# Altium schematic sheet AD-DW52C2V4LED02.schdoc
size 127 x 101 mm
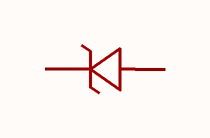
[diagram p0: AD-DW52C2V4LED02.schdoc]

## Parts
D?  ad-dw52c2v4led02  [WBFBP-02C_L1.0-W0.6-RD]  (value not drawn)

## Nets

Not connected (* = marked no-connect by the designer): D? 1(A) 2(C)

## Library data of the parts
D? = ad-dw52c2v4led02: 二极管配置:1个独立式;稳压值(标称值):2.4V;稳压值(范围值):2.2V~2.6V;耗散功率(Pd):100mW;; Manufacturer: CJ(江苏长电/长晶); AddInBom: yes; Diode Configuration: 1个独立式; Zener Voltage(Nom): 2.4V; Reverse Leakage Current (Ir): 50uA@1V; Pd - Power Dissipation: 100mW; Impedance(Zzt): 100Ω; Impedance(Zzk): 600Ω; Operating Junction Temperature Range: -55℃~+150℃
